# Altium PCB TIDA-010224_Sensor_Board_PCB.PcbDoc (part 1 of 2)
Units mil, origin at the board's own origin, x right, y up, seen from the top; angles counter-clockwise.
Board outline 1083.05 x 1167.48 mil, 4 copper layers (L1-Top Layer, L2-GND Layer, L3-PWR Layer, L4-Bottom Layer), stack 61.6 mil thick; 74 components, 35 nets, 283 pads, 146 vias.
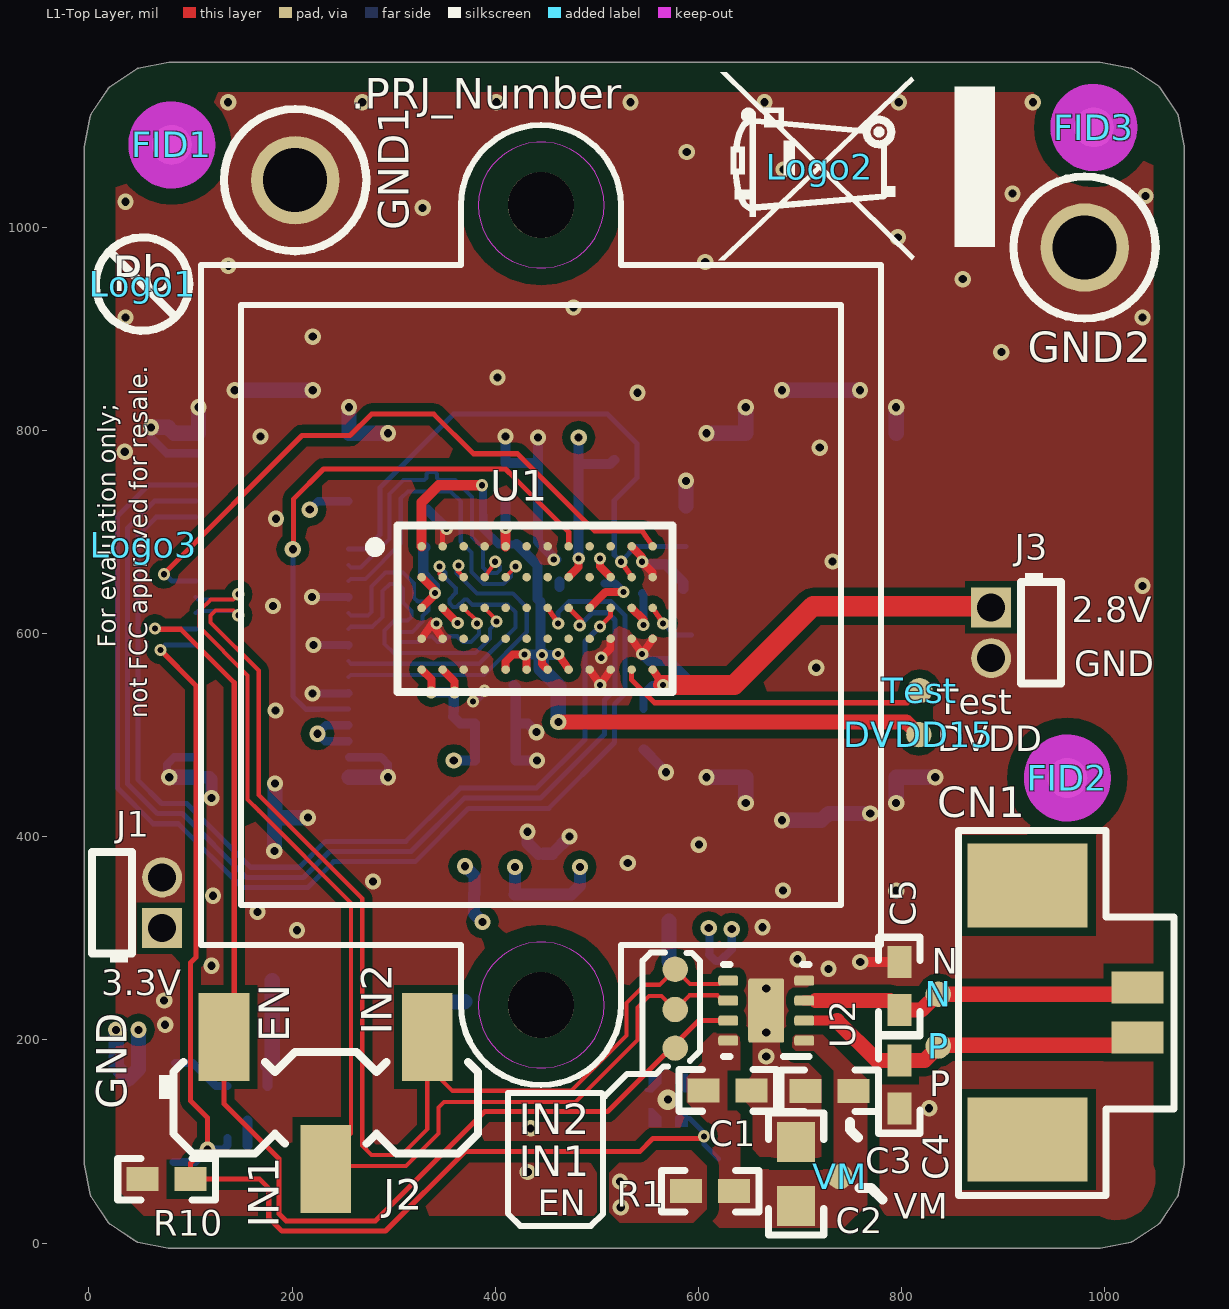
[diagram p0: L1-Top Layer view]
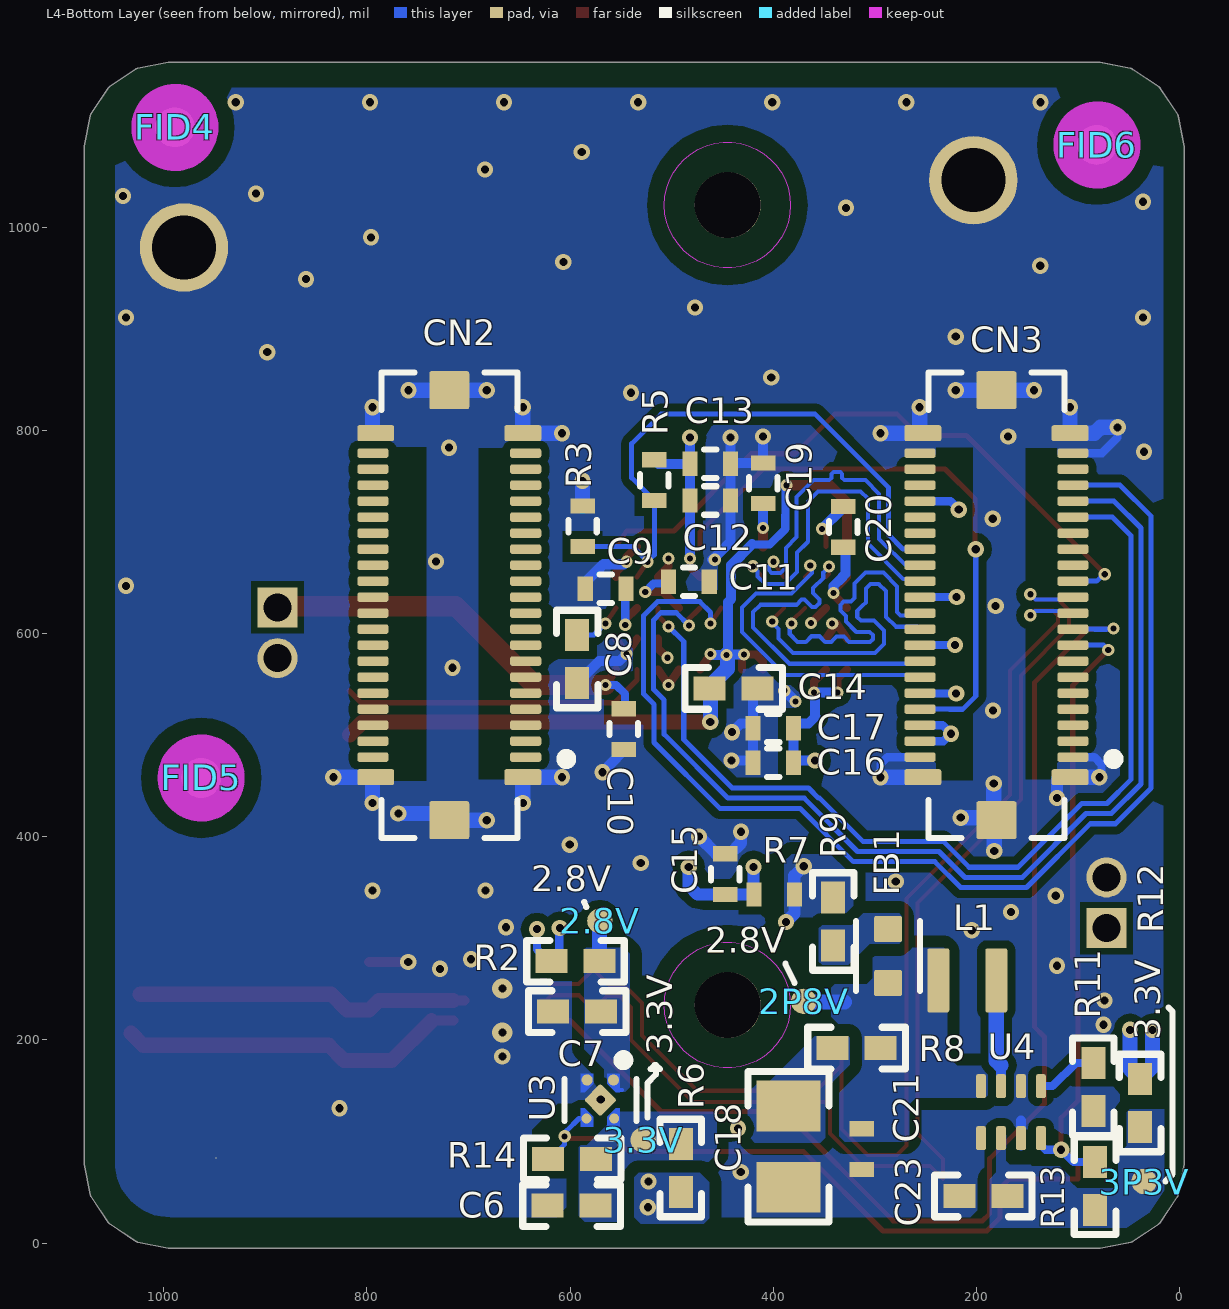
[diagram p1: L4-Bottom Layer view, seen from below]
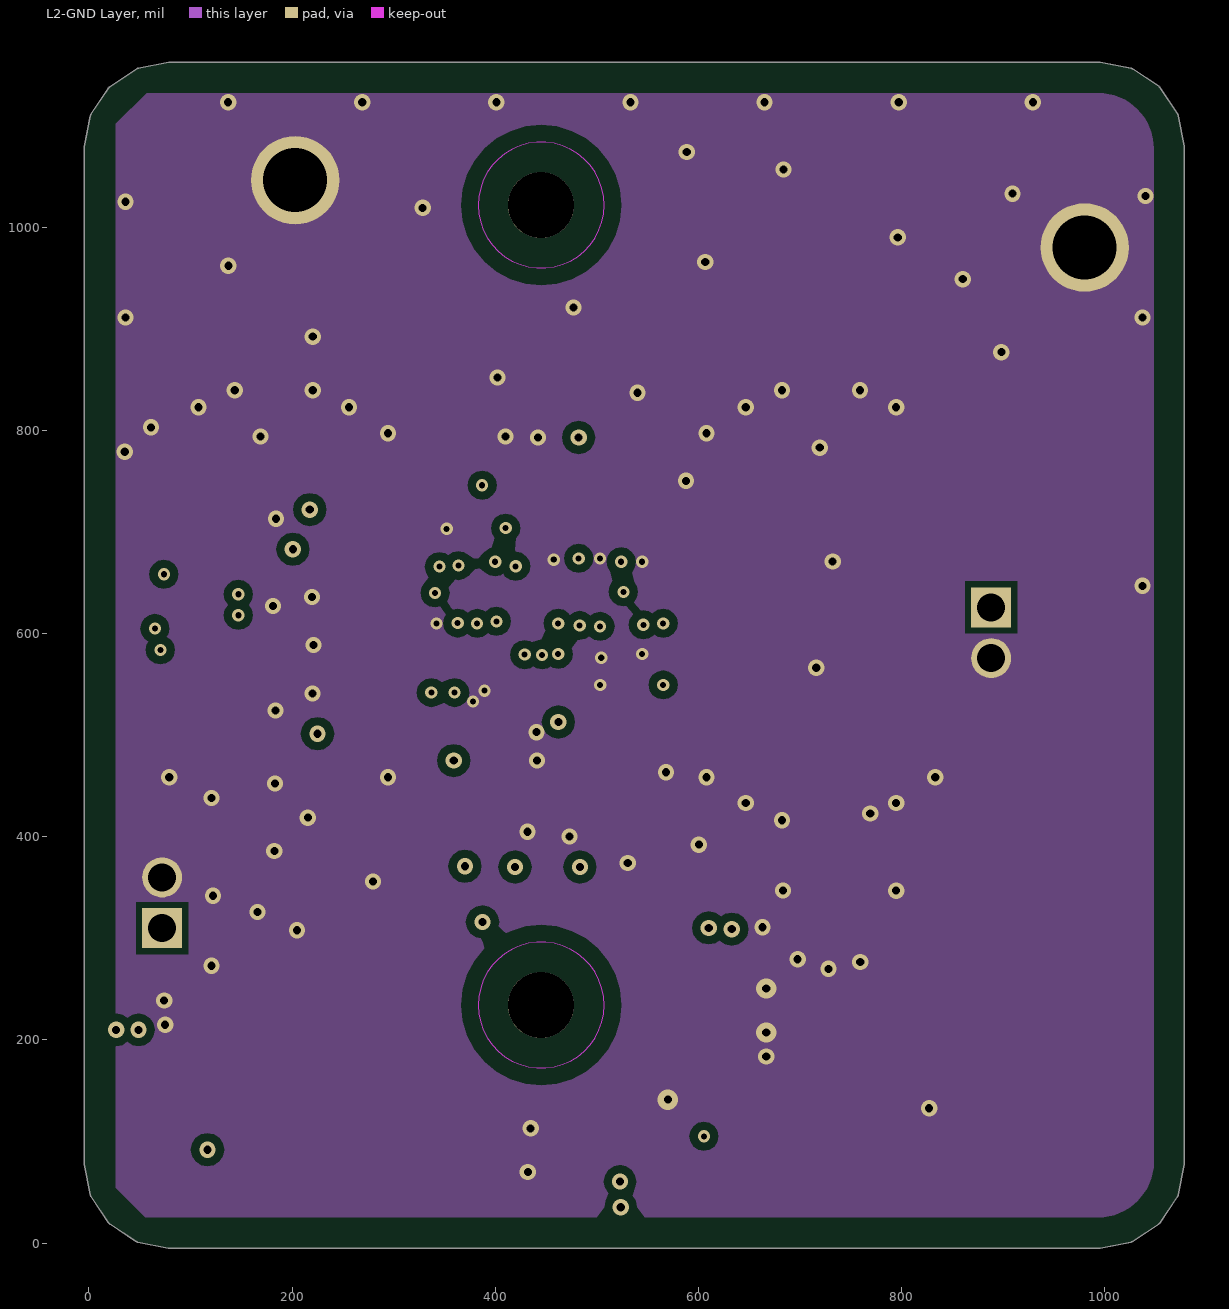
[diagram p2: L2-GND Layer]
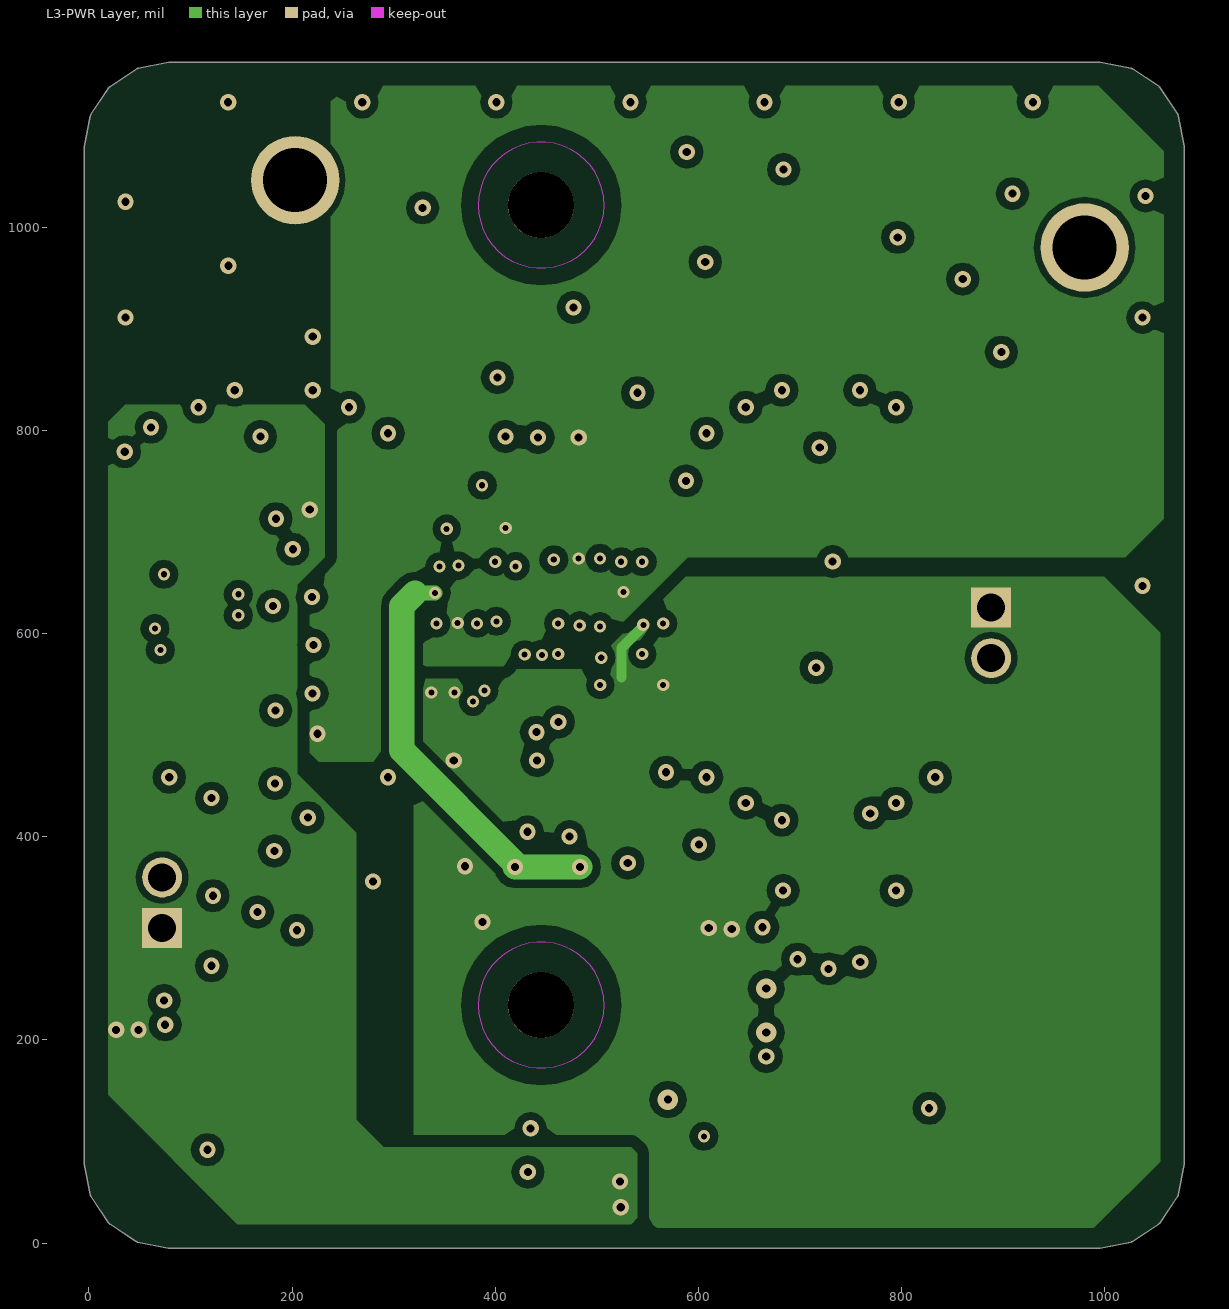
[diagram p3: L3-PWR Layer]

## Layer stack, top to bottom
Top Solder: solder mask 0.3, Solder Resist, Dk 3.5
L1-Top Layer: signal copper 1.4
Dielectric1: core 8, FR-4 High Tg, Dk 4.5
L2-GND Layer: signal copper 1.4
Dielectric 2: prepreg 40, FR-4 High Tg, Dk 4.5
L3-PWR Layer: signal copper 1.4
Dielectric 3: core 8, FR-4 High Tg, Dk 4.5
L4-Bottom Layer: signal copper 1.4
Bottom Solder: solder mask 0.3, Solder Resist, Dk 3.5

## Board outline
2.07,45.82 cw(c6.24,48.6) 1.33,47.62 -4.67,77.76 cw(c0.25,78.74) -4.77,78.74 -4.77,1078.26 cw(c0.25,1078.26) -4.67,1079.24 1.33,1109.37 cw(c6.24,1108.39) 2.09,1111.2 19.13,1136.71 cw(c23.31,1133.94) 20.53,1138.11 46.08,1155.18 46.85,1155.69 cw(c49.64,1151.52) 48.66,1156.44 78.48,1162.37 cw(c79.45,1157.45) 79.45,1162.47 994.52,1162.47 cw(c994.52,1157.45) 995.5,1162.37 1025.64,1156.38 cw(c1024.66,1151.46) 1027.44,1155.63 1052.99,1138.56 cw(c1050.21,1134.39) 1054.39,1137.16 1071.44,1111.65 1071.45,1111.63 1071.44,1111.65 cw(c1067.28,1108.85) 1072.2,1109.83 1078.19,1079.69 cw(c1073.27,1078.72) 1078.29,1078.72 1078.29,78.74 cw(c1073.27,78.74) 1078.19,77.76 1072.2,47.63 cw(c1067.28,48.61) 1071.44,45.8 1071.45,45.82 1071.44,45.8 1054.39,20.29 1054.38,20.28 1054.39,20.29 cw(c1050.21,23.06) 1052.99,18.89 1027.44,1.82 cw(c1024.66,5.99) 1025.64,1.08 995.5,-4.92 cw(c994.52,0) 994.52,-5.01 79.32,-5.01 cw(c78.99,-0.01) 78.01,-4.93 47.88,1.07 cw(c48.86,5.98) 46.05,1.82 20.54,18.87 20.53,18.88 20.54,18.87 cw(c23.31,23.05) 19.14,20.27

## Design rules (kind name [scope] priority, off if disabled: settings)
AcuteAngle [All] p1: minimum=4.50000000000000E+0001 checktracksonly=FALSE
AssemblyTestPointUsage [All] p1: valid=2
BoardOutlineClearance BoardOutlineClearance_MountingHoles [OnCopper and InComponentClass('Mounting Holes')] p1: gap=30 ignorepadtopadclearanceinfootprint=FALSE
BoardOutlineClearance BoardOutlineClearance_Poly [OnCopper and InPoly] p2: gap=14 ignorepadtopadclearanceinfootprint=FALSE
BoardOutlineClearance [OnCopper and Not InComponentClass('Logo') and not InComponentClass('FiducialMark') and not InRegion(1000,500,4000,800)] p3: gap=14 ignorepadtopadclearanceinfootprint=FALSE
Clearance Clearance_U3 [InPadClass('U3')] p1: gap=4.7 ignorepadtopadclearanceinfootprint=FALSE
Clearance Clearance_Keepouts [IsKeepOut vs InPoly] p2: gap=16 ignorepadtopadclearanceinfootprint=FALSE
Clearance Clearance_Poly_poly [InPoly vs InPoly] p3: gap=15 ignorepadtopadclearanceinfootprint=FALSE except(0: Arc-Hole Track-Hole SMDPad-Hole THPad-Hole Via-Hole Fill-Hole Poly-Hole Region-Hole Text-Hole; 12: Fill-Fill Fill-Poly Fill-Region Poly-Poly Poly-Region Region-Region; 20: Arc-SMDPad Arc-THPad Arc-Text Track-SMDPad Track-THPad Track-Text SMDPad-SMDPad SMDPad-THPad SMDPad-Via SMDPad-Text THPad-THPad THPad-Via THPad-Text Via-Via Via-Text Fill-Text Poly-Text Region-Text Text-Text)
Clearance Clearance_Poly [InPolygon] p4: gap=8 ignorepadtopadclearanceinfootprint=FALSE except(6: THPad-Fill THPad-Poly THPad-Region THPad-Hole)
Clearance [All] p5: gap=5 ignorepadtopadclearanceinfootprint=FALSE except(0: Arc-Track Arc-SMDPad; 4: SMDPad-Region)
ComponentClearance ComponentClearance_MountingHoles_FiducialMarks [InComponentClass('Mounting Holes') vs InComponentClass('FiducialMark')] p1: gap=10 collisioncheckmode=3 verticalgap=10 showdistances=FALSE
ComponentClearance ComponentClearance_Shunt [InComponentClass('Header') vs InComponentClass('Shunt')] p2: gap=0 collisioncheckmode=3 verticalgap=0 showdistances=FALSE
ComponentClearance ComponentClearance_Logo [InComponentClass('Logo')] p3: gap=5 collisioncheckmode=3 verticalgap=5 showdistances=FALSE
ComponentClearance ComponentClearance_ScrewToNut [(HasFootprint('NY PMS 440 0025 PH')) vs (HasFootprint('Keystone_1902C'))] p4: gap=5 collisioncheckmode=3 verticalgap=10 showdistances=FALSE
ComponentClearance ComponentClearance_MountingHoles [InComponentClass('Mounting Holes')] p5: gap=250 collisioncheckmode=3 verticalgap=100000 showdistances=FALSE
ComponentClearance ComponentClearance_SmallPassives [HasFootprint('0201*') or HasFootprint('0402*') or HasFootprint('0508') or HasFootprint('0603*') or HasFootprint('0612') or HasFootprint('0805*') or HasFootprint('0815*') or HasFootprint('0830*') or HasFootprint('1206*') or HasFootprint('1210*') or HasFootprint('1808*') or HasFootprint('1812*') or HasFootprint('1825*') or HasFootprint('2010*') or HasFootprint('2220*') or HasFootprint('2225*') or HasFootprint('2512*') or HasFootprint('2728*') or HasFootprint('3518*') vs HasFootprint('0201*') or HasFootprint('0402*') or HasFootprint('0508') or HasFootprint('0603*') or HasFootprint('0612') or HasFootprint('0805*') or HasFootprint('0815*') or HasFootprint('0830*') or HasFootprint('1206*') or HasFootprint('1210*') or HasFootprint('1808*') or HasFootprint('1812*') or HasFootprint('1825*') or HasFootprint('2010*') or HasFootprint('2220*') or HasFootprint('2225*') or HasFootprint('2512*') or HasFootprint('2728*') or HasFootprint('3518*')] p6: gap=5 collisioncheckmode=3 verticalgap=5 showdistances=FALSE
ComponentClearance ComponentClearance_THtoSMT [IsThruComponent vs IsSMTComponent] p7: gap=5 collisioncheckmode=3 verticalgap=5 showdistances=FALSE
ComponentClearance ComponentClearance_THtoTH [IsThruComponent vs IsThruComponent] p8: gap=0 collisioncheckmode=3 verticalgap=10 showdistances=FALSE
ComponentClearance [All] p9: gap=10 collisioncheckmode=3 verticalgap=10 showdistances=FALSE
DiffPairsRouting [All] p1: maxlimit=7 minlimit=7 mostfreqgap=7 toplayer_minwidth=4 toplayer_maxwidth=4 toplayer_prefwidth=4 midlayer1_minwidth=4 midlayer1_maxwidth=4 midlayer1_prefwidth=4 midlayer2_minwidth=4 midlayer2_maxwidth=4 midlayer2_prefwidth=4 bottomlayer_minwidth=4 bottomlayer_maxwidth=4 bottomlayer_prefwidth=4 maxuncoupledlength=1000
FabricationTestPointUsage TestPointUsage [All] p1: valid=2 allowmultiple=FALSE
FabricationTestpoint Testpoint [All] p1: side=3 testpointundercomponent=TRUE minsize=40 maxsize=100 preferedsize=60 minholesize=0 maxholesize=40 preferedholesize=32 testpointgrid=1 allowsidetop=TRUE allowsidebottom=TRUE usegrid=TRUE gridtolerance=0.01
FanoutControl Fanout_LCC [IsLCC] p1: bgadir=Out bgaviamode=Centered fanoutstyle=Auto fanoutdirection=Alternating viagrid=1 // Fanout_LCC (Default Rule)
FanoutControl Fanout_BGA [IsBGA] p2: bgadir=Out bgaviamode=Centered fanoutstyle=Auto fanoutdirection=Alternating viagrid=1 // Fanout_BGA (Default Rule)
FanoutControl Fanout_Default [All] p4: bgadir=Out bgaviamode=Centered fanoutstyle=Auto fanoutdirection=Alternating viagrid=1 // Fanout_Default (Default Rule)
FanoutControl Fanout_Small [(CompPinCount < 5)] p5: bgadir=Out bgaviamode=Centered fanoutstyle=Auto fanoutdirection=OutThenIn viagrid=1 // Fanout_Small (Default Rule)
HoleSize [All] p1: absolutevalues=TRUE maxlimit=251 minlimit=6 maxpercent=80.000 minpercent=20.000
MinimumAnnularRing MinimumAnnularRing_ThermalPadVias [IsVia and InAnyComponent] p1: minimumring=3
MinimumAnnularRing [All] p2: minimumring=3
MinimumSolderMaskSliver MinimumSolderMaskSliver_Logo [InComponentClass('Logo') vs InComponentClass('Logo')] p1: minsoldermaskwidth=0.7
MinimumSolderMaskSliver [All] p2: minsoldermaskwidth=3
PlaneClearance [All] p1: clearance=10
PlaneConnect [All] p1: planeconnectstyle=Relief reliefexpansion=10 reliefentries=4 reliefconductorwidth=10 reliefairgap=10
PolygonConnect PolygonConnectThermalVia [isvia] p1: connectstyle=Direct reliefconductorwidth=10 reliefentries=4 polygonreliefangle="90 Angle" airgapwidth=10
PolygonConnect PolygonConnectThermalPad [((ObjectKind = 'Pad') And (((Name Like 'U*') or (Name Like 'D*')) and (InComponentClass('TIDA-00183_pg-4_Driver') or InComponentClass('TIDA-00183_pg-5_OP_Connector')))) or ((ObjectKind = 'Pad') And (Name like 'U61*'))] p2: connectstyle=Direct reliefconductorwidth=10 reliefentries=4 polygonreliefangle="90 Angle" airgapwidth=10
PolygonConnect [All] p3: connectstyle=Direct reliefconductorwidth=10 reliefentries=4 polygonreliefangle="90 Angle" airgapwidth=5
RoutingVias ThermalPadVias [IsVia and InAnyComponent] p1: holewidth=7.87 width=19.68 viastyle="Through Hole" minholewidth=6 minwidth=12 maxholewidth=12.99 maxwidth=23.62
RoutingVias [All] p2: holewidth=16 width=34 viastyle="Through Hole" minholewidth=6 minwidth=12 maxholewidth=40 maxwidth=65
SilkToBoardRegionClearance [Not ((IsComment or IsDesignator) And (Hide <> 'False')) and not InRegion(1000,500,4000,800)] p1:
SilkToSilkClearance SilkToSilkClearance_Pb-FreeLogo [(HasFootprint('Pb-Free_Overlay_Medium') OR HasFootprint('Pb-Free_Overlay_Small')) vs (HasFootprint('Pb-Free_Overlay_Medium') OR HasFootprint('Pb-Free_Overlay_Small'))] p1: silktosilkclearance=0
SilkToSilkClearance [All] p2: silktosilkclearance=2
SilkToSolderMaskClearance SilkToComponentPadClearance [IsPad and InAnycomponent] p1: minsilkscreentomaskgap=3 clearancetoexposedcopper=TRUE
SilkToSolderMaskClearance "Silk to Solder Mask Opening" [All] p2: minsilkscreentomaskgap=2 clearancetoexposedcopper=FALSE
SolderMaskExpansion [All] p1: expansion=1.97
Width [All] p1: maxlimit=100 minlimit=4 preferedwidth=5 checkconnectedcopper=TRUE
14 further rules are at their usual default settings.

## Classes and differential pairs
component class Header: J1 J2 J3
component class Sensor_Board_Hardware: FID1 FID2 FID3 FID4 FID5 FID6 Logo1 Logo2 Logo3 ZZ1 ZZ2 ZZ3 ZZ4
component class AssemblyNote: ZZ1 ZZ2 ZZ3 ZZ4
component class FiducialMark: FID1 FID2 FID3 FID4 FID5 FID6
differential pair SN: +SN_IN2 -SN_IN1
differential pair MRXC0: +MRXCP0 -MRXCN0
differential pair MRXD0: +MRXDP0 -MRXDN0
differential pair MRXD1: +MRXDP1 -MRXDN1

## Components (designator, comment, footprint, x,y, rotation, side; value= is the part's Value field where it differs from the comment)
2.8V "2.8V" TP_25MIL-SMT 570.63,317.18 r90 bottom
2P8V "2.8V" TP_25MIL-SMT 370,238 r180 bottom
3.3V "3.3V" TP_25MIL-SMT 528.14,101.64 r90 bottom
3P3V "3.3V" TP_25MIL-SMT 34.91,60.71 r90 bottom
C1 "GRM155R71C104KA88D" 0402 628.6,150.4 r180 top value=0.1uF
C2 "GRM188Z71A106MA73D" 0603 696,68 r90 top value=10uF
C3 "GRM155R71C104KA88D" 0402 729,150 r0 top value=0.1uF
C4 "GRM155R71C104KA88D" 0402 797.63,156.16 r90 top value=0.1uF
C5 "GRM155R71C104KA88D" 0402 797.63,253.16 r90 top value=0.1uF
C6 "C1005X7S1A105K050BC" 0402 598.52,37 r0 bottom value=1uF
C7 "C1005X7S1A105K050BC" 0402 593,228 r0 bottom value=1uF
C8 "C1005X7S1A105K050BC" 0402 593,575 r270 bottom value=1uF
C9 "GRM155R71C104KA88D" 0402S 564.98,644.03 r180 bottom value=0.1uF
C10 "GRM155R71C104KA88D" 0402S 546.98,506 r90 bottom value=0.1uF
C11 "GRM155R71C104KA88D" 0402S 483,651 r0 bottom value=0.1uF
C12 "GRM155R71C104KA88D" 0402S 462,731 r0 bottom value=0.1uF
C13 "GRM155R71C104KA88D" 0402S 462,767 r0 bottom value=0.1uF
C14 "C1005X7S1A105K050BC" 0402 439,546 r180 bottom value=1uF
C15 "GRM155R71C104KA88D" 0402S 447.39,363.22 r270 bottom value=0.1uF
C16 "GRM155R71C104KA88D" 0402S 400,473 r180 bottom value=0.1uF
C17 "GRM155R71C104KA88D" 0402S 400,507 r180 bottom value=0.1uF
C18 "GRM21BR61A476ME15L" 0805_HV 385,95 r270 bottom value=47uF
C19 "GRM155R71C104KA88D" 0402S 410,748 r270 bottom value=0.1uF
C20 "GRM155R71C104KA88D" 0402S 331,705 r270 bottom value=0.1uF
C21 "C0402C106M9PACTU" 0402_070 313,92.56 r270 bottom value=10uF
C23 "GRM155R61A475MEAAD" 0402 193.22,46.5 r0 bottom value=4.7uF
CN1 "53398-0271" 0533980271 978,227 r270 top
CN2 "FX12B-40S-0.4SV(30)" FP-FX12B-40S-0.4SV(30)_RCPT40-MFG#1 718.88,627.94 r90 bottom
CN3 "FX12B-40S-0.4SV(30)" FP-FX12B-40S-0.4SV(30)_RCPT40-MFG#2 180.31,627.94 r90 bottom
DVDD15 "DVDD" TP_25MIL-SMT 816.86,500.54 r90 top
EN "EN" TP_25MIL-SMT 577,192 r90 top
FB1 "BLM18KG121TN1D" FP-BLM18KG121TN1D_0603-MFG 287,282.57 r90 bottom
FID1 "Fiducial" Fiducial10-20 81.5,1081 r0 top
FID2 "Fiducial" Fiducial10-20 963,457.92 r0 top
FID3 "Fiducial" Fiducial10-20 989,1098.23 r0 top
FID4 "Fiducial" Fiducial10-20 989,1098.23 r180 bottom
FID5 "Fiducial" Fiducial10-20 963,457.92 r180 bottom
FID6 "Fiducial" Fiducial10-20 81.5,1081 r180 bottom
GND1 "GND" Keystone5005 203,1046.27 r0 top
GND2 "GND" Keystone5005 980,980 r90 top
IN1 "IN1" TP_25MIL-SMT 577,230 r90 top
IN2 "IN2" TP_25MIL-SMT 577,269.61 r90 top
J1 "GRPB021VWCN-RC" Sullins_xxxB021VWCN 72,335 r90 top
J2 "M20-8770342" Harwin_M20-87703 233,138.04 r0 top
J3 "GRPB021VWCN-RC" Sullins_xxxB021VWCN 888,600.81 r270 top
L1 "DFE201612E-2R2M=P2" DFE201612E 209,258.62 r0 bottom value=2.2uH
Logo1 "Pb-Free Symbol" Pb-Free_Overlay_Small 52.76,944 r0 top
Logo2 "WEEE logo" WEEE_Minimum 719.24,1059.67 r90 top
Logo3 "FCC disclaimer" FCC_disclaimer_stacked 54,687.39 r90 top
N "N" TP_25MIL-SMT 836,245 r90 top
P "P" TP_25MIL-SMT 836,194 r90 top
R1 "Resistor" 0402 611.46,51.12 r180 top value=0
R2 "Resistor" 0402 594.63,277.6 r180 bottom value=0
R3 "RC0402FR-0710KL" 0402S 587.69,705.69 r270 bottom value=10.0k
R5 "RC0402FR-0710KL" 0402S 517,751 r90 bottom value=10.0k
R6 "Resistor" 0402 491,74 r270 bottom value=0
R7 "Resistor" 0402S 399,343.22 r180 bottom value=0
R8 "ERJ-2BQFR33X" 0402 318,192 r180 bottom value=0.33
R9 "Resistor" 0402 341,316.62 r270 bottom value=0
R10 "ERJ-2RKF4701X" 0402 76.38,63 r0 top value=4.70k
R11 "CRCW040228K7FKED" 0402 85,153.9 r90 bottom value=28.7k
R12 "Resistor" 0402 39,138 r90 bottom value=0
R13 "Resistor" 0402 83.28,56.38 r90 bottom value=0
R14 "Resistor" 0402 598,83 r0 bottom value=0
Test "Test" TP_25MIL-SMT 817.63,543.9 r90 top
U1 "SP2329" FP-SP2329_CSP60-IPC_C 438.93,624.53 r0 top locked
U2 "DRV8837CDSG" DSG0008A 666.62,229 r180 top
U3 "TPS7A2028PDQNR" DQN0004A-MFG 570.2,140.8 r270 bottom
U4 "TPS62840DLCR" DLC0008B 166,129 r90 bottom
VM "VM" TP_25MIL-SMT 739,65.53 r0 top
ZZ1 "These assemblies must comply with workmanship standards IPC-A-610 Class 2, unless otherwise specified." AssemblyNote -3319.15,3245.72 r0 top
ZZ2 "These assemblies must be clean and free from flux and all contaminants. Use of no clean flux is not acceptable." AssemblyNote -3319.15,3334.28 r0 top
ZZ3 "These assemblies are ESD sensitive, ESD precautions shall be observed." AssemblyNote -3319.15,3422.83 r0 top
ZZ4 "This Assembly Note is for PCB labels only" AssemblyNoteLabel -3319.15,3531.72 r0 top

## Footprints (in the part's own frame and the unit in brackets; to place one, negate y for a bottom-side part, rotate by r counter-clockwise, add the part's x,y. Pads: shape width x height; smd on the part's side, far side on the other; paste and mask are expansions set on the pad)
0402 [mm] "0402 from SM-752 data"
  rect 0.8x0.6 smd: 1(-0.6,0) 2(0.6,0)
  silkscreen extent -1.22,-0.52 1.22,0.52, body extent -0.55,-0.3 0.55,0.3, height 0.6
0402_070 [mil] "SMD, 2-Leads, Body 1.2x0.7mm, Height 0.7mm"
  rect 15x24 smd: 1(-20,0) 2(20,0)
  body extent -24,-14 24,14, height 28
0402S [mil] "Based on C0402S footprint from PADS legacy"
  rect 15x24 smd: 1(-20,0) 2(20,0)
  silkscreen extent -6,-14 6,14, body extent -22,-12 22,12, height 24
0603 [mm] "0603 from SM-752 data"
  rect 1x0.95 smd: 1(-0.8,0) 2(0.8,0)
  silkscreen extent -1.52,-0.69 1.52,0.69, body extent -0.87,-0.47 0.87,0.47, height 1
0805_HV [mil] "0805 with 30mil clearance between pads"
  rect 50x63 smd: 1(-40,0) 2(40,0)
  silkscreen extent -74,-40 74,40, body extent -43,-29 43,29, height 57
0533980271 [mm] "Molex PicoBlade 2 pos from documents no. SD-53398-033 dated 2006-04-02"
  rect 0.8x1.3 smd: 1(-0.625,1.375) 2(0.625,1.375)
  rect 2.1x3 smd: 3(-3.175,-1.375) 4(3.175,-1.375)
  silkscreen extent -4.55,-3.1 4.57,2.29, body extent -3.86,-2.44 3.79,1.76, height 4.8
AssemblyNote [mil] "Assembly Note"
AssemblyNoteLabel [mil] "Assembly Note for PCB Labels"
DFE201612E [mm] "MuRata recommended"
  rrect18% 0.55x1.6 smd: 1(-0.725,0) 2(0.725,0)
  body extent -1.1,-0.9 1.1,0.9, height 1.2
DLC0008B [mm] "VSON-HR-8"
  rrect40% 0.6x0.25 smd: 1(-0.65,0.75) 2(-0.65,0.25) 3(-0.65,-0.25) 4(-0.65,-0.75) 5(0.65,-0.75) 6(0.65,-0.25) 7(0.65,0.25) 8(0.65,0.75)
  body extent -0.75,-1 0.75,1, height 1
DQN0004A-MFG [mm]
  round 0.279 smd paste-1000 mask-1000: 1(-0.505,0.33) 2(-0.505,-0.33)
  round 0.251 smd paste-1000 mask-1000: 3(0.459,-0.346) 4(0.459,0.346)
  rrect17% 0.58x0.58 smd rot 135 paste-1000 mask+0.025: 5(0,0)
  L1-Top Layer region: -0.66,-0.485 -0.2,-0.485 -0.2,-0.385 -0.41,-0.175 -0.66,-0.175
  L1-Top Layer region: 0.66,0.485 0.2,0.485 0.2,0.385 0.41,0.175 0.66,0.175
  L1-Top Layer region: 0.66,-0.485 0.2,-0.485 0.2,-0.385 0.41,-0.175 0.66,-0.175
  L1-Top Layer region: -0.66,0.485 -0.2,0.485 -0.2,0.385 -0.41,0.175 -0.66,0.175
  silkscreen extent -1.12,-0.9 0.53,0.9, body extent -0.5,-0.5 0.5,0.5, height 0.4
DSG0008A [mm] "SON, 8-Leads, Body 2x2mm, Pitch 0.5mm, Thermal Pad 1.6x0.9mm, TI Recommended"
  rrect40% 0.5x0.25 smd: 1(-0.95,0.75) 2(-0.95,0.25) 3(-0.95,-0.25) 4(-0.95,-0.75) 5(0.95,-0.75) 6(0.95,-0.25) 7(0.95,0.25) 8(0.95,0.75)
  rrect14% 0.9x0.7 on Top Paste: 9(0,0.45) 9(0,-0.45)
  rrect11% 0.9x1.6 smd paste-0.45: 9(0,0)
  silkscreen extent -1.08,-1.15 1.07,1.15, body extent -1,-1 1,1, height 0.77
FCC_disclaimer_stacked [mil]
Fiducial10-20 [mm]
  round 1 smd mask+0.5: 1(0,0)
  L1-Top Layer keep-out circle w1.178: c0,0 r0.5
FP-BLM18KG121TN1D_0603-MFG [mm]
  rrect15% 0.65x0.7 smd paste+0 mask+0: 1(-0.675,0) 2(0.675,0)
  silkscreen extent -0.87,-0.8 0.87,0.8, body extent -0.8,-0.4 0.8,0.4, height 0.75
FP-FX12B-40S-0.4SV(30)_RCPT40-MFG#1 [mm]
  rrect43% 0.23x0.78 smd paste-1000 mask+0.041: 1(-3.8,-1.91) 2(-3.8,1.91) 3(-3.4,-1.91) 4(-3.4,1.91) 5(-3,-1.91) 6(-3,1.91) 7(-2.6,-1.91) 8(-2.6,1.91) 9(-2.2,-1.91) 10(-2.2,1.91) 11(-1.8,-1.91) 12(-1.8,1.91) 13(-1.4,-1.91) 14(-1.4,1.91) 15(-1,-1.91) 16(-1,1.91) 17(-0.6,-1.91) 18(-0.6,1.91) 19(-0.2,-1.91) 20(-0.2,1.91) 21(0.2,-1.91) 22(0.2,1.91) 23(0.6,-1.91) 24(0.6,1.91) 25(1,-1.91) 26(1,1.91) 27(1.4,-1.91) 28(1.4,1.91) 29(1.8,-1.91) 30(1.8,1.91) 31(2.2,-1.91) 32(2.2,1.91) 33(2.6,-1.91) 34(2.6,1.91) 35(3,-1.91) 36(3,1.91) 37(3.4,-1.91) 38(3.4,1.91) 39(3.8,-1.91) 40(3.8,1.91)
  rrect25% 0.4x0.92 smd paste-1000 mask+0.041: 41(-4.3,1.84) 42(4.3,1.84) 45(-4.3,-1.84) 46(4.3,-1.84)
  rrect11% 0.95x1 smd paste-1000 mask+0.041: 43(-5.375,0) 44(5.375,0)
  silkscreen extent -5.82,-3.05 5.82,1.7, body extent -5.67,-2.1 5.67,2.1, height 1.5
FP-FX12B-40S-0.4SV(30)_RCPT40-MFG#2 [mm]
  rrect43% 0.23x0.78 smd paste-1000 mask+0.043: 1(-3.8,-1.91) 2(-3.8,1.91) 3(-3.4,-1.91) 4(-3.4,1.91) 5(-3,-1.91) 6(-3,1.91) 7(-2.6,-1.91) 8(-2.6,1.91) 9(-2.2,-1.91) 10(-2.2,1.91) 11(-1.8,-1.91) 12(-1.8,1.91) 13(-1.4,-1.91) 14(-1.4,1.91) 15(-1,-1.91) 16(-1,1.91) 17(-0.6,-1.91) 18(-0.6,1.91) 19(-0.2,-1.91) 20(-0.2,1.91) 21(0.2,-1.91) 22(0.2,1.91) 23(0.6,-1.91) 24(0.6,1.91) 25(1,-1.91) 26(1,1.91) 27(1.4,-1.91) 28(1.4,1.91) 29(1.8,-1.91) 30(1.8,1.91) 31(2.2,-1.91) 32(2.2,1.91) 33(2.6,-1.91) 34(2.6,1.91) 35(3,-1.91) 36(3,1.91) 37(3.4,-1.91) 38(3.4,1.91) 39(3.8,-1.91) 40(3.8,1.91)
  rrect25% 0.4x0.92 smd paste-1000 mask+0.043: 41(-4.3,1.84) 42(4.3,1.84) 45(-4.3,-1.84) 46(4.3,-1.84)
  rrect11% 0.95x1 smd paste-1000 mask+0.043: 43(-5.375,0) 44(5.375,0)
  silkscreen extent -5.82,-3.05 5.82,1.7, body extent -5.67,-2.1 5.67,2.1, height 1.5
FP-SP2329_CSP60-IPC_C [mil]
  round 8.37 smd paste+0 mask+2: A1(-111.46,61.32) A2(-90.79,61.32) A3(-70.12,61.32) A4(-49.45,61.32) A5(-28.78,61.32) A6(-8.11,61.32) A7(12.56,61.32) A8(33.23,61.32) A9(53.9,61.32) A10(74.57,61.32) A11(95.24,61.32) A12(115.91,61.32) B1(-111.46,31.01) B2(-90.79,31.01) B3(-70.12,31.01) B4(-49.45,31.01) B5(-28.78,31.01) B6(-8.11,31.01) B7(12.56,31.01) B8(33.23,31.01) B9(53.9,31.01) B10(74.57,31.01) B11(95.24,31.01) B12(115.91,31.01) C1(-111.46,0.69) C2(-90.79,0.69) C3(-70.12,0.69) C4(-49.45,0.69) C5(-28.78,0.69) C6(-8.11,0.69) C7(12.56,0.69) C8(33.23,0.69) C9(53.9,0.69) C10(74.57,0.69) C11(95.24,0.69) C12(115.91,0.69) D1(-111.46,-29.62) D2(-90.79,-29.62) D3(-70.12,-29.62) D4(-49.45,-29.62) D5(-28.78,-29.62) D6(-8.11,-29.62) D7(12.56,-29.62) D8(33.23,-29.62) D9(53.9,-29.62) D10(74.57,-29.62) D11(95.24,-29.62) D12(115.91,-29.62) E1(-111.46,-59.94) E2(-90.79,-59.94) E3(-70.12,-59.94) E4(-49.45,-59.94) E5(-28.78,-59.94) E6(-8.11,-59.94) E7(12.56,-59.94) E8(33.23,-59.94) E9(53.9,-59.94) E10(74.57,-59.94) E11(95.24,-59.94) E12(115.91,-59.94)
  silkscreen extent -162,-82 135,82, body extent -139,-86 139,86, height 10
Harwin_M20-87703 [mm] "Header, 2.54mm, 3x1, SMT"
  rect 1.27x2.2 smd: 1(-2.54,1.65) 2(0,-1.65) 3(2.54,1.65)
  silkscreen extent -4.17,-1.27 3.81,1.27, body extent -3.81,-2.54 3.81,2.54, height 9.93
Keystone5005 [mil] "Keystone Compact loops"
  round 87 hole 63: 1(0,0)
  silkscreen extent -70,-70 70,70, body extent -63,-63 62,63, height 225
Pb-Free_Overlay_Small [mil]
  silkscreen extent -46,-46 46,46
Sullins_xxxB021VWCN [mm] "Header, 1.27mm, 2x1, RA, TH"
  rect 1x1 hole 0.7: 1(-0.635,0)
  round 1 hole 0.7: 2(0.635,0)
  silkscreen extent -1.49,0.75 1.27,1.75, body extent -1.27,-0.2 1.27,4.75, height 2.14
TP_25MIL-SMT [mil]
  round 25 smd mask+1.5: 1(0,0)
WEEE_Minimum [mil] "WEEElie bin"
  silkscreen extent -92,-172 93,100

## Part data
2.8V 2P8V 3.3V 3P3V DVDD15 EN IN1 IN2 N P Test VM: library part CMP-0078143-2, "TEST POINT.  No entry in BOM.", Manufacturer=N/A
C1 C3 C4 C5 C9 C10 C11 C12 C13 C15 C16 C17 C19 C20: library part CMP-0006641-2, "CAP, CERM, 0.1 uF, 16 V, +/- 10%, X7R, 0402", Cap_Case=0402, Manufacturer=MuRata, Supplier Part Number 1=490-3261-1-ND, TempCo=X7R, Tolerance_%=10%, Value1=Unknown, Value2=16V, ValueDisplayed=0.1uF
C2: library part CMP-0007497-5, "CAP, CERM, 10 uF, 10 V, +/- 20%, X7R, 0603", Cap_Case=0603, Manufacturer=MuRata, Supplier Part Number 1=81-GRM188Z71A106MA3D, TempCo=X7R, Tolerance_%=20%, Value1=Unknown, Value2=10V, ValueDisplayed=10uF
C6 C7 C8 C14: library part CMP-0006300-2, "CAP, CERM, 1 uF, 10 V, +/- 10%, X7S, 0402", Cap_Case=0402, Manufacturer=TDK, Supplier Part Number 1=445-9116-1-ND, TempCo=X7S, Tolerance_%=10%, Value1="0.011416 ohm", Value2=10V, ValueDisplayed=1uF
C18: library part CMP-0078699-1, "CAP, CERM, 47 µF, 10 V,+/- 20%, X5R, 0805", Cap_Case=0805, Manufacturer=MuRata, Supplier Part Number 1=490-9961-1-ND, TempCo=X5R, Tolerance_%=20%, Value2=10V
C21: library part CMP-0081134-1, "CAP, CERM, 10 µF, 6.3 V,+/- 20%, X5R, 0402", Cap_Case=0402, Manufacturer=Kemet, Supplier Part Number 1=80-C0402C106M9P, TempCo=X5R, Tolerance_%=20%, Value1="0.001 ohm", Value2=6.3V, ValueDisplayed=10µF
C23: library part CMP-0006582-2, "CAP, CERM, 4.7 uF, 10 V, +/- 20%, X5R, 0402", Cap_Case=0402, Manufacturer=MuRata, Supplier Part Number 1=490-14306-1-ND, TempCo=X5R, Tolerance_%=20%, Value1=Unknown, Value2=10V, ValueDisplayed=4.7uF
CN1: library part CMP-0055117-1, "Plug, SMT, Vertical, 1.25mm, 1x2", Manufacturer=Molex, Supplier Part Number 1=WM7606CT-ND
CN2 CN3: library part CMP-0089231-1, "40 Position Connector Receptacle, Outer Shroud Contacts Surface Mount", Current_A=3dA, Digikey Part Number=FX12B-40S-0.4SV(30)-ND, Manufacturer=Hirose, Mouser Part Number=798-FX12B40S04SV30, Operating Temperature Range="-55°C to +85°C", Voltage_V=30V
FB1: library part CMP-0089995-1, "120 Ohms @ 100MHz 1 Power Line Ferrite Bead 0603 (1608 Metric) 3A 30mOhm", Digikey Part Number=490-5254-1-ND, Impedance At Frequency="120O @ 100MHz", Manufacturer=Murata, Mouser Part Number=81-BLM18KG121TN1D, Operating Temperature Range="-55°C to +125°C", Test Frequency=100MHz, Tolerance_%=25%
FID1 FID2 FID3 FID4 FID5 FID6: library part CMP-0077181-1, "Fiducial mark.  There is nothing to buy or mount.", Manufacturer=N/A
GND1 GND2: library part CMP-0055142-1, "Test Point, Compact, Red, TH", Color=Red, Manufacturer=Keystone, PartNumber=5005, Supplier Part Number 1=36-5005-ND
J1 J3: library part CMP-0054582-1, "Header, 1.27 mm, 2x1, Gold, R/A, TH", Color=Black, Manufacturer="Sullins Connector Solutions", Supplier Part Number 1=S9016E-02-ND
J2: library part CMP-0075319-1, "Header, 2.54mm, 3x1, Gold, SMT", Color=Black, Current_A=3A, Manufacturer=Harwin, Supplier Part Number 1=952-1951-ND
L1: library part CMP-0080775-1, "Inductor, Shielded, Metal Composite, 2.2 µH, 1.8 A, 0.116 ohm, SMD", Manufacturer=MuRata, PartNumber=DFE201612E-2R2M{}P2, Value1="0.116 ohm", Value2=1.8A, ValueDisplayed=2.2µH
Logo1: library part CMP-0074839-1
Logo2: library part CMP-0074769-1
Logo3: library part CMP-0074847-1, "FCC_disclaimer"
R1 R2 R6 R7 R9 R12 R13 R14: library part CMP-0026822-3, "RES, 0, 5%, 0.063 W, AEC-Q200 Grade 0, 0402", Manufacturer=Vishay-Dale, PartNumber=CRCW04020000Z0ED, Power_W=63mW, Supplier Part Number 1=541-0.0JCT-ND, TempCo="200 ppm/C", Tolerance_%=5%, Value2=0.063W, Value_Code=0000, ValueDisplayed=0
R3 R5: library part CMP-0078669-1, "RES, 10.0 k, 1%, 0.063 W, 0402", Manufacturer="Yageo America", Power_W=63mW, Supplier Part Number 1=311-10.0KLRCT-ND, TempCo="100 ppm/C", Tolerance_%=1%, Value2=0.063W, Value_Code=10k0, ValueDisplayed=10.0k
R8: library part CMP-0026635-2, "RES, 0.33, 1%, 0.125 W, AEC-Q200 Grade 0, 0402", Manufacturer=Panasonic, Power_W=125mW, Supplier Part Number 1=P.33AKCT-ND, TempCo="250 ppm/C", Tolerance_%=1%, Value2=0.125W, Value_Code=R330, ValueDisplayed=0.33
R10: library part CMP-0026700-1, "RES, 4.70 k, 1%, 0.1 W, 0402", Manufacturer=Panasonic, Power_W=100mW, Supplier Part Number 1=P4.70KLCT-ND, TempCo="100 ppm/C", Tolerance_%=1%, Value2=0.1W, Value_Code=4k70, ValueDisplayed=4.70k
R11: library part CMP-0026220-2, "RES, 28.7 k, 1%, 0.063 W, AEC-Q200 Grade 0, 0402", Manufacturer=Vishay-Dale, Power_W=63mW, Supplier Part Number 1=541-28.7KLCT-ND, TempCo="100 ppm/C", Tolerance_%=1%, Value2=0.063W, Value_Code=28k7, ValueDisplayed=28.7k
U1: library part CMP-0088584-2, "1/2.7-Inch 2-Mega Pixel CMOS Image Sensor", Manufacturer=SuperPix, Max Supply Voltage=3V, Min Supply Voltage=1.7V, Operating Temperature Range="-30°C to +85°C"
U2: library part CMP-0013449-3, "1-A Low-Voltage H-Bridge Driver, DSG0008A (WSON-8)", Alternate Manufacturer="Texas Instruments"
U3: library part CMP-0090215-1, "300-mA, Ultra-Low-Noise, Low-IQ, High PSRR LDO", Dropout Voltage=690mV, Manufacturer="Texas Instruments", Max Supply Voltage=6V, Min Supply Voltage=1.6V, Nominal Supply Current=6.5uA, Operating Temperature Range="-40°C to +125°C", Output Voltage=0.8-5.5V
U4: library part CMP-0081431-4, "Ultra low IQ Step Down Converter, DLC0008A (VSON-HR-8)", Alternate Manufacturer="Texas Instruments", Operating Temperature Range="-40 to 125 C"
ZZ1: library part CMP-0077238-1
ZZ2: library part CMP-0077237-1
ZZ3: library part CMP-0077236-1
ZZ4: library part CMP-0003616-3

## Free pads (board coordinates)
  round 65 hole 65 unplated mask+5: ""(444.87,234.34) ""(444.87,1021.75)

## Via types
v1: diameter 16, hole 8, L1-Top Layer to L4-Bottom Layer, tented both sides, 103 vias
v2: diameter 12, hole 6, L1-Top Layer to L4-Bottom Layer, tented both sides, 40 vias
v3: diameter 20, hole 8, L1-Top Layer to L4-Bottom Layer, tented top, 2 vias
v4: diameter 20, hole 8, L1-Top Layer to L4-Bottom Layer, 1 vias

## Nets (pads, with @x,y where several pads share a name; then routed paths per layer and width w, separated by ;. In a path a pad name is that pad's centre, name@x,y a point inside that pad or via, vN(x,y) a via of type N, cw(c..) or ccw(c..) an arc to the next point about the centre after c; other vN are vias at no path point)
DVDD15: C14.1 DVDD15.1 U1.A1 U1.E5 U1.E6 U1.E7 U1.E8 | length 852.6
  L1-Top Layer w8: U1.E5@410.15,564.59 410.15,572.28 417.15,579.28 v2(428.87,579.28) 430.82,577.34 U1.E6@430.82,564.59 ; v2(446,579) 446,570.08 U1.E7@451.49,564.59 ; v2(461.82,579.75) U1.E8@472.16,564.59
  L1-Top Layer w10: U1.A1@327.47,685.85 327.47,729.2 344.29,746.02 v2(387,746.02)
  L1-Top Layer w15: v1(462,513) 804.4,513 DVDD15.1@816.86,500.54
  L4-Bottom Layer w8: v2(387,746.02) 388,745.02 388,716.36 388.13,716.22 388.13,703.12 403.4,687.85 420.97,687.85
  L4-Bottom Layer w10: 420.97,687.85 441.5,667.32 441.5,634.09 444.59,631 v2@444.59,582.42 ; v2(428.87,579.28) 445.72,579.28 v2(446,579) 461.06,579 v2(461.82,579.75)
  L4-Bottom Layer w15: v2@445.72,579.28 445.13,578.7 445.13,565.49 C14.1@462.62,548 ; C14.1@461.82,545.67 461.82,513.82 461.5,513.5 v1(462,513)
GND: C1.1 C2.2 C3.1 C4.1 C5.2 C6.2 C7.2 C8.2 C9.1 C10.1 C11.1 C12.1 C13.1 C14.2 C15.1 C16.1 C17.1 C18.2 C19.1 C20.1 C21.2 C23.2 CN2.41 CN2.42 CN2.43 CN2.44 CN2.45 CN2.46 CN3.1 CN3.2 CN3.10 CN3.16 CN3.22 CN3.39 CN3.40 CN3.41 CN3.42 CN3.43 CN3.44 CN3.45 CN3.46 GND1.1 GND2.1 J1.2 J3.2 R3.1 R10.1 R11.1 U1.A2 U1.A4 U1.A7 U1.A11 U1.B10 U1.B12 U1.D1 U1.D2 U1.D10 U1.D11 U1.D12 U1.E3 U1.E4 U1.E9 U1.E10 U2.4 U2.9@666.62,229 U3.2 U3.5 U4.1 U4.3 U4.6 | length 1939.4
  L1-Top Layer w5: U1.A2@348.14,685.85 348.14,699.77 351.49,703.12 v2(352.08,703.12)
  L1-Top Layer w8: U1.D1@327.47,594.91 337.81,610.07 339.17,608.07 U1.D2@348.14,594.91 ; U1.E9@492.83,564.59 v2(503.16,549.43) U1.E10@513.5,564.59 ; 503,666.02 U1.B10@513.5,655.54 ; 503,666.09 v2(503,674) ; v2(504.23,576.22) 513.5,585.49 U1.D10@513.5,594.91 ; U1.D11@534.16,594.91 v2(544.5,579.75) U1.D12@554.83,594.91 ; U1.A11@534.16,685.85 544.5,675.52 v2(544.5,670.69) 554.83,660.35 U1.B12@554.83,655.54
  L1-Top Layer w10: v1(759.21,276.78) C5.2@797.63,276.78
  L4-Bottom Layer w8: v1(61.02,803) 61.02,792.85 76.32,777.55 CN3.39@107.86,777.55 ; v1(79.04,458.65) 76.97,456.58 76.97,471.31 84,478.33 CN3.1@105.11,478.33 CN3.1@106.61,478.33 ; v1(219.52,636) 255.32,636 CN3.22@255.51,635.81 ; v1(220,541) 255.18,541 CN3.10@255.51,541.32 ; v1(221,588.73) 255.34,588.73 CN3.16@255.51,588.57 ; CN3.2@255.9,478.34 287.43,478.34 294.41,471.35 v1(294.41,458.65) ; v2(342,610) v2@342.93,609.07
  L4-Bottom Layer w10: 156,120.52 156.16,111.42 U4.3@156.16,103.41 U4.3@156.16,96.03 ; C20.1@333,722 333.2,722 v2(352.08,703.12) ; v2(378,533) 388.81,543.81 v2(389.17,543.81) ; v1(410,794) C19.1@410,768 441,768 C13.1@442,767 ; C14.2@418.06,549.43 420.49,547 420,546.51 C17.1@420,511.54 ; v1(440.52,503) 431.98,511.54 C17.1@420,511.54 ; v1(441,475) 420,475 C17.1@420,511.54 ; v1(442,793) C13.1@442,767 ; v2(457.5,672.76) v2@459.75,672.76 ; v2@460.25,672.76 v2@459.75,672.76 ; C11.1@463,646 C11.1@463,651 ; v2(544.5,579.75) 551.25,573 571.38,573 C8.2@593,551.38 ; v2(544.5,670.69) 547,668.19 567.23,668.19 585,650.42 C9.1@584.98,644.03 ; C10.1@545.98,486 562,469.98 562,469.46 v1(568,463.46) ; C13.1@442,767 C12.1@442,731 442,690.51 v2@459.75,672.76
  L4-Bottom Layer w12: CN3.45@107.87,458.65 118.78,458.65 120.7,456.73 v1(120.7,438.08) ; v1(431.68,404.9) 431.68,393.93 C15.1@442.39,383.22 ; C15.1@447.39,383.22 456.08,383.22 v1(473.08,400.22)
  L4-Bottom Layer w15: v1(61.02,803) 78,803 83.77,797.23 CN3.46@107.87,797.23 v1(107.87,822.75) ; v1(79.04,458.65) CN3.45@107.87,458.65 ; v1(143.44,839.56) v1(220.32,839.56) ; CN3.43@182.39,416.85 183,417.46 v1(183,452.4) ; v1(182.5,386) 182.5,416.32 185,418.82 v1(215.42,418.82) ; v1(255.89,822.75) 255.89,797.23 v1(294.41,797.23) ; CN3.41@256,458.54 255.89,458.65 v1(294.41,458.65) ; R3.1@587.69,725.69 v1(587.69,750.31) ; v1(607.93,458.65) CN2.45@646.44,458.65 v1(646.44,433.13) ; v1(607.92,797.23) CN2.46@646.44,797.23 v1(646.44,822.75) ; v1(682.02,416.32) 720.46,416.32 720.78,416 727.78,423 v1(769,423) ; v1(682.02,839.56) v1(758.89,839.56) ; v1(794.47,433.13) 794.47,458.65 v1(832.98,458.65) ; CN2.42@794.47,797.23 v1(794.47,822.75)
  other v1: 432,70 434.72,113 827,132.82 666.62,183.72 75,215 74,238.84 728,270 120.7,273 697.53,279.51 204.65,308 663,311 166,326 122,342 683.22,347.23 794.47,347 279.46,356 530.37,374.23 600.31,392.23 183.72,524.34 715.79,566.36 181.07,627.19 1037,647 732,671 184,713.01 35.19,779 719.24,783 168.77,794 540,837 402,852 898,877 220.32,892.24 36,911 1037,911 476.91,921 860,948.87 137.2,962 606.63,965.69 796,990 328.45,1019 36,1025 1040,1030.64 909,1033 683.7,1056.85 588.44,1074 137,1123 269,1123 401,1123 533,1123 665,1123 797,1123 929,1123
  other v3: 666.62,207.35 666.62,250.65
  other v4: 569.83,141.28
IR-CUT_N: C5.1 CN1.1 N.1 U2.3 | length 329.2
  L1-Top Layer w10: U2.3@704.02,238.84 715,238.84
  L1-Top Layer w15: 715,238.84 788.33,238.84 C5.1@797.63,229.54 819.51,229.54 834.98,245 N.1@836,245 CN1.1@1023,245
IR-CUT_P: C4.2 CN1.2 P.1 U2.2 | length 345
  L1-Top Layer w10: 714.69,219.16 736.43,219.16 736.59,219
  L1-Top Layer w15: 736.43,218.84 775.5,179.78 C4.2@797.63,179.78 822.54,179.78 837.54,194.78 1020.2,194.78 CN1.2@1032.13,206.72
IR_CUT_EN: CN3.17 EN.1 J2.1 U2.7 | length 1216.5
  L1-Top Layer w5: v2(65,605) 65.77,604.23 90.38,604.23 143,551.61 143,213 J2.1@133,203 133,137.15 187,83.15 187,29 194,22 282,22 389.5,129.5 510.5,129.5 577,196 600.16,219.16 U2.7@629.21,219.16
  L4-Bottom Layer w5: v2(65,605) 65.68,604.32 72.32,604.32 72.41,604.23 83.59,604.23 83.68,604.32 CN3.17@105.11,604.32
MRXCN0: CN3.18 U1.C4 | length 312.1
  L1-Top Layer w4: U1.C4@389.48,625.22 v2@399.33,615.37
  L4-Bottom Layer w4: CN3.18@255.51,604.32 257.94,606.74 279.24,606.74 289,616.51 289,641.8 296.19,648.98 304.47,648.98 308.91,644.54 308.91,630.54 312,627.44 317.35,622.1 317.35,616.35 313.74,612.74 300.74,612.74 291,603 291,589.87 300.02,580.85 380.52,580.85 394.76,595.08 394.76,604.37 400,609.62 400,611 v2(401,612)
MRXCP0: CN3.20 U1.C3 | length 311.6
  L1-Top Layer w4: U1.C3@368.81,625.22 v2@382.3,611.74
  L4-Bottom Layer w4: CN3.20@255.51,620.06 257.83,617.74 274.68,617.74 278,621.07 278,646.35 291.65,660 295.58,660 ; 295.6,659.98 309.02,659.98 319.91,649.09 319.91,635.09 323.63,631.37 330.87,631.37 334,628.24 334,622.72 328.35,617.09 328.35,611.79 318.3,601.74 305.3,601.74 302,598.44 302,594.43 304.58,591.85 325.4,591.85 330.55,597 337.78,597 342.93,591.85 348.85,591.85 354.36,597.36 362.49,597.36 368,591.85 375.97,591.85 383.76,599.64 v2@383.76,609.47
  other v2: 382,610
MRXDN0: CN3.12 U1.B3 | length 327
  L1-Top Layer w4: v2(363.63,666.97) 363.63,661.97 363,661.34 U1.B3@368.81,655.54
  L4-Bottom Layer w4: CN3.12@255.51,557.07 257.74,559.31 378.82,559.31 388.62,559.31 430.91,601.59 430.91,611.39 430.91,625.59 417.13,639.36 392.37,639.36 381.87,639.36 361.77,659.46 361.77,666.97 361.77,668.77 v2(363.63,666.97) v2(363.63,666.97)
MRXDN1: CN3.24 U1.B5 | length 324.3
  L1-Top Layer w4: U1.B5@410.15,655.54 420,665.38 v2(420,666.19)
  L4-Bottom Layer w4: CN3.24@255.51,651.56 257.88,653.93 272.07,653.93 306.87,688.74 306.87,732.92 313.95,740 355.95,740 365.96,729.99 365.96,690.39 376.65,679.7 376.65,660.49 388.43,648.72 407.79,648.72 415.41,656.33 415.41,661.6 v2(420,666.19)
MRXDP0: CN3.14 U1.B2 | length 327.4
  L1-Top Layer w4: v2(345,666) 345,658.67 U1.B2@348.14,655.54
  L4-Bottom Layer w4: CN3.14@255.51,572.82 258.02,570.31 384.07,570.31 419.91,606.15 419.91,621.03 412.58,628.36 377.31,628.36 372.22,633.45 369.45,633.45 362,626 358.52,626 354.65,629.87 354.65,633.65 361,640 361,644.67 350.77,654.9 350.77,660.23 v2(345,666)
MRXDP1: CN3.26 U1.B4 | length 324.5
  L1-Top Layer w4: U1.B4@389.48,655.54 v2(399.82,670.69)
  L4-Bottom Layer w4: CN3.26@255.51,667.31 257.88,664.93 267.51,664.93 295.87,693.3 295.87,737.48 309.39,751 330,751 332.15,753.15 332.15,757.15 334,759 340.85,759 342.69,757.16 342.69,753.31 345,751 360.5,751 376.96,734.54 376.96,694.95 387.65,684.25 387.65,665.05 392.99,659.72 401.69,659.72 404.41,662.44 404.41,666.1 v2(399.82,670.69)
Net2.8V_1: 2.8V.1 C7.1 R2.2 U3.1 | length 44.7
  L4-Bottom Layer w4: 548.78,150.7 553.59,150.7 553.84,150.95
  L4-Bottom Layer w15: R2.2@571,277.6 2.8V.1@571,317.18
Net2P8V_1: 2P8V.1 C21.1 FB1.1 L1.2 R8.2 U4.8 | length 40.3
  L4-Bottom Layer w15: 330,237.38 369.38,237.38 2P8V.1@370,238
Net3.3V_1: 3.3V.1 C6.1 R6.1 R14.1 U3.4
Net3P3V_1: 3P3V.1 C23.1 R12.1 R13.1 U4.2
NetC1_2: C1.2 C2.1 C3.2 R1.1 U2.1 U2.8 VM.1
NetC8_1: C8.1 U1.C12 | length 50.9
  L1-Top Layer w5: U1.C12@554.83,625.22 v2(565.17,610.06)
  L4-Bottom Layer w5: v2(565.17,610.06) 576.61,598.62 C8.1@593,598.62
NetC18_1: C18.1 R8.1
NetFB1_2: FB1.2 R9.2
NetL1_1: L1.1 U4.7 | length 105.9
  L4-Bottom Layer w10: U4.7@175.84,154.59 175.84,175.05
  L4-Bottom Layer w15: 175.84,175.05 180.46,179.66 L1.1@180.46,258.62
NetR11_2: R11.2 U4.5 | length 61
  L4-Bottom Layer w8: R11.2@85,177.52 102.13,177.52 125.06,154.59 U4.5@136.47,154.59
NetTest_1: Test.1 U1.E11 | length 308
  L1-Top Layer w5: U1.E11@534.16,564.59 534.16,554.32 556.56,531.93 805.66,531.93 Test.1@817.63,543.9
SID: CN3.28 R3.2 R5.1 U1.B11 | length 594.7
  L1-Top Layer w5: v2(523.83,670.69) U1.B11@534.16,655.54
  L4-Bottom Layer w5: CN3.28@255.51,683.06 272.2,683.06 286.37,697.23 286.37,743.62 358.75,816 510.28,816 539.4,786.89 539.4,753.4 R5.1@517,731 517,677.52 v2(523.83,670.69) ; v2@523.83,671.24 538.28,685.69 R3.2@587.69,685.69
SN_CLK: CN3.8 U1.A8 | length 577.4
  L1-Top Layer w5: v1(200.69,683) 201.5,683.81 201.5,732.58 230.92,762 410,762 419,753 472.23,699.77 472.23,685.92 U1.A8@472.16,685.85
  L4-Bottom Layer w5: v1(200.69,683) 200.69,538.39 213.58,525.5 226.42,525.5 226.5,525.58 CN3.8@255.51,525.58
